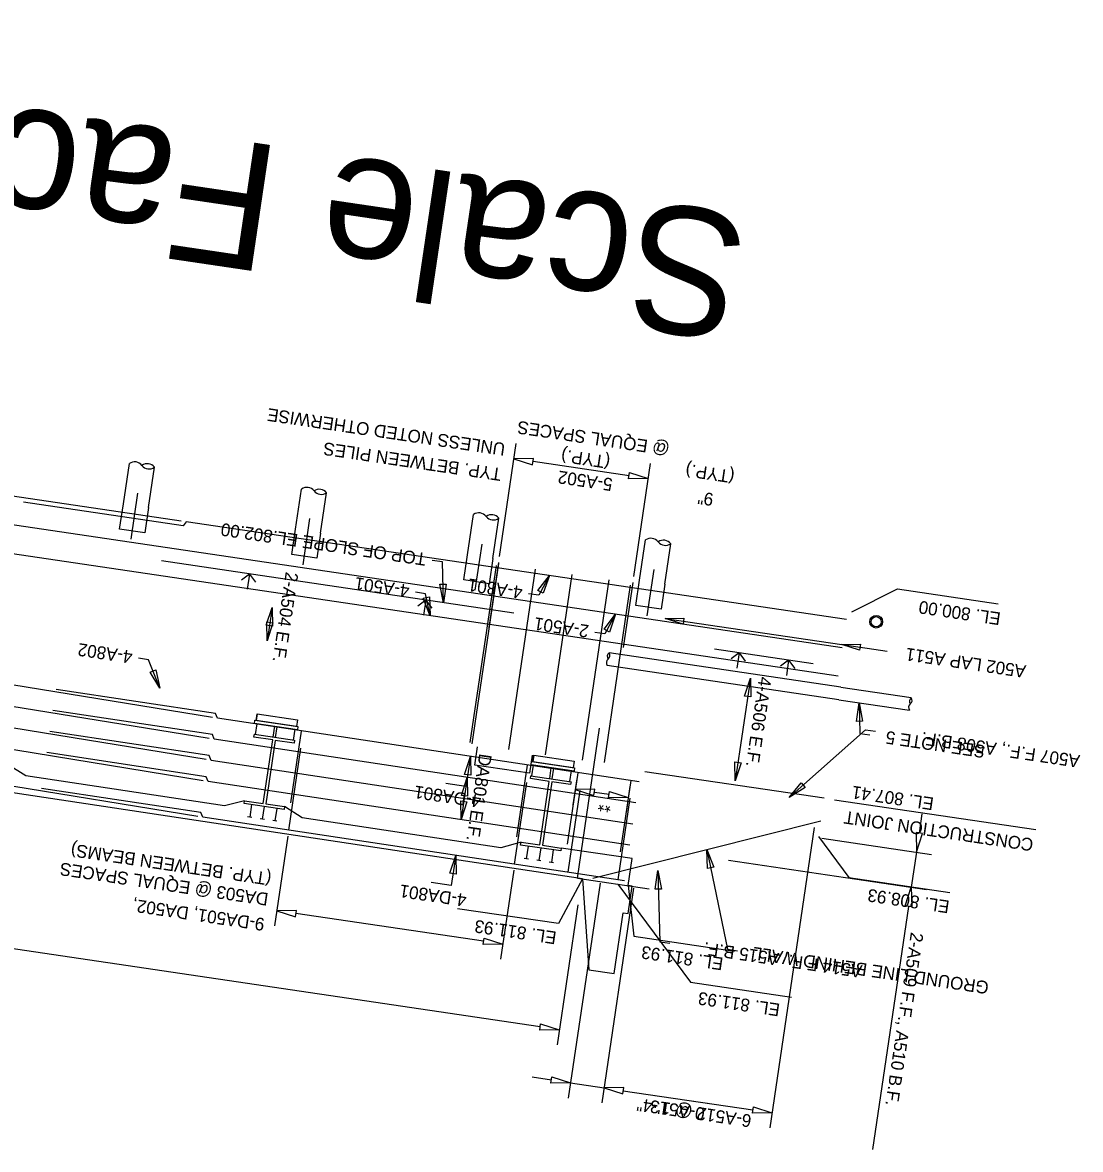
# Model space of a CAD drawing. Extents: x 1467956 to 1469946, y 573734 to 574139.
# Drawn here: x 1469049.93 to 1469091.48, y 574051.68 to 574095.95 of the extents above; entities that cross this region are included whole.
import ezdxf

# ---------------------------------------------------------------- set-up
doc = ezdxf.new("R2010")
doc.units = 0
for name, color, linetype in [('BR_P_Beam_Object', 7, 'Continuous'), ('BR_P_Beam_Stl_Det_Hidden', 7, 'Continuous'), ('BR_P_Brg_Pad_Object', 7, 'Continuous'), ('BR_P_Dia_Hidden', 7, 'Continuous'), ('BR_P_Dia_Reinforcing', 7, 'Continuous'), ('BR_P_Gen_NonPerf_Pipe', 7, 'Continuous'), ('BR_P_Gen_Text', 7, 'Continuous'), ('BR_P_Slab_Object', 7, 'Continuous'), ('BR_P_Sub_Const_Joint', 7, 'Continuous'), ('BR_P_Sub_Deep_Centerline', 7, 'Continuous'), ('BR_P_Sub_Deep_Hidden', 7, 'Continuous'), ('BR_P_Sub_Deep_Object', 7, 'Continuous'), ('BR_P_Sub_Foot_Reinforcing', 7, 'Continuous'), ('BR_P_Sub_Hidden', 7, 'Continuous'), ('BR_P_Sub_Text', 7, 'Continuous'), ('Default', 7, 'Continuous')]:
    doc.layers.add(name, color=color, linetype=linetype)

# ---------------------------------------------------------------- blocks, each defined once
blk = doc.blocks.new('arrowOhio')
at = {"layer": 'Default'}
blk.add_lwpolyline([(0.00381, 0.000635), (0.00381, -0.000635), (0, 0)], close=True, dxfattribs=at)

msp = doc.modelspace()

# ---------------------------------------------------------------- linework, layer by layer
at = {"layer": 'BR_P_Beam_Object'}
for p, q in [((1469059.015, 574067.879), (1469059.032, 574067.992)), ((1469059.753, 574067.77), (1469059.015, 574067.879)), ((1469059.032, 574067.992), (1469060.607, 574067.759)), ((1469059.384, 574065.276), (1469059.753, 574067.77)), ((1469059.853, 574067.755), (1469059.483, 574065.261)), ((1469060.591, 574067.646), (1469059.853, 574067.755)), ((1469060.607, 574067.759), (1469060.591, 574067.646)), ((1469069.878, 574066.251), (1469069.895, 574066.364)), ((1469070.616, 574066.141), (1469069.878, 574066.251)), ((1469069.895, 574066.364), (1469071.47, 574066.131)), ((1469070.247, 574063.648), (1469070.616, 574066.141)), ((1469070.715, 574066.127), (1469070.346, 574063.633)), ((1469071.453, 574066.018), (1469070.715, 574066.127)), ((1469071.47, 574066.131), (1469071.453, 574066.018)), ((1469058.629, 574065.272), (1469058.646, 574065.385)), ((1469060.205, 574065.039), (1469058.629, 574065.272)), ((1469058.646, 574065.385), (1469059.384, 574065.276)), ((1469058.922, 574065.229), (1469058.849, 574064.734)), ((1469059.417, 574065.155), (1469059.344, 574064.661)), ((1469059.483, 574065.261), (1469060.221, 574065.152)), ((1469059.912, 574065.082), (1469059.838, 574064.588)), ((1469060.221, 574065.152), (1469060.205, 574065.039)), ((1469058.932, 574064.722), (1469058.767, 574064.746)), ((1469059.426, 574064.649), (1469059.261, 574064.673)), ((1469059.921, 574064.575), (1469059.756, 574064.6)), ((1469069.492, 574063.644), (1469069.509, 574063.757)), ((1469069.509, 574063.757), (1469070.247, 574063.648)), ((1469071.067, 574063.411), (1469069.492, 574063.644)), ((1469069.785, 574063.6), (1469069.712, 574063.106)), ((1469070.279, 574063.527), (1469070.206, 574063.033)), ((1469070.346, 574063.633), (1469071.084, 574063.524)), ((1469070.774, 574063.454), (1469070.701, 574062.959)), ((1469071.084, 574063.524), (1469071.067, 574063.411)), ((1469069.794, 574063.094), (1469069.629, 574063.118)), ((1469070.289, 574063.02), (1469070.124, 574063.045)), ((1469070.783, 574062.947), (1469070.618, 574062.972))]:
    msp.add_line(p, q, dxfattribs=at)
at = {"layer": 'BR_P_Beam_Stl_Det_Hidden'}
for p, q in [((1469059.073, 574067.986), (1469059.136, 574068.409)), ((1469059.77, 574067.883), (1469059.833, 574068.306)), ((1469059.869, 574067.868), (1469059.932, 574068.291)), ((1469060.566, 574067.765), (1469060.629, 574068.188)), ((1469069.936, 574066.358), (1469069.998, 574066.78)), ((1469070.633, 574066.255), (1469070.695, 574066.677)), ((1469070.732, 574066.24), (1469070.794, 574066.663)), ((1469071.429, 574066.137), (1469071.491, 574066.559))]:
    msp.add_line(p, q, dxfattribs=at)
at = {"layer": 'BR_P_Brg_Pad_Object'}
for p, q in [((1469059.145, 574068.797), (1469059.107, 574068.539)), ((1469059.039, 574068.423), (1469059.057, 574068.547)), ((1469060.726, 574068.173), (1469059.039, 574068.423)), ((1469059.057, 574068.547), (1469060.744, 574068.297)), ((1469060.733, 574068.562), (1469060.694, 574068.304)), ((1469060.744, 574068.297), (1469060.726, 574068.173)), ((1469069.901, 574066.795), (1469069.92, 574066.918)), ((1469069.92, 574066.918), (1469071.606, 574066.669)), ((1469070.007, 574067.169), (1469069.969, 574066.911)), ((1469071.595, 574066.934), (1469071.557, 574066.676)), ((1469071.588, 574066.545), (1469069.901, 574066.795)), ((1469071.606, 574066.669), (1469071.588, 574066.545))]:
    msp.add_line(p, q, dxfattribs=at)
for points in [[(1469060.733, 574068.562), (1469060.694, 574068.304), (1469059.107, 574068.539), (1469059.145, 574068.797)], [(1469071.595, 574066.934), (1469071.557, 574066.676), (1469069.969, 574066.911), (1469070.007, 574067.169)]]:
    msp.add_lwpolyline(points, close=True, dxfattribs=at)
at = {"layer": 'BR_P_Dia_Hidden'}
for q in [(1469072.594, 574068.231), (1469074.541, 574061.928)]:
    msp.add_line((1469071.723, 574062.345), q, dxfattribs=at)
at = {"layer": 'BR_P_Dia_Reinforcing'}
for p, q in [((1469057.382, 574068.654), (1469035.698, 574072.185)), ((1469057.26, 574067.826), (1469035.575, 574071.358)), ((1469057.137, 574066.999), (1469035.453, 574070.53)), ((1469057.015, 574066.171), (1469035.33, 574069.703)), ((1469057.506, 574068.81), (1469051.244, 574069.755)), ((1469057.384, 574067.983), (1469051.121, 574068.928)), ((1469057.58, 574068.624), (1469057.506, 574068.81)), ((1469074.146, 574066.124), (1469057.58, 574068.624)), ((1469056.807, 574064.767), (1469035.123, 574068.299)), ((1469057.261, 574067.155), (1469050.999, 574068.1)), ((1469057.457, 574067.797), (1469057.384, 574067.983)), ((1469074.023, 574065.297), (1469057.457, 574067.797)), ((1469060.87, 574068.11), (1469060.455, 574065.302)), ((1469057.139, 574066.328), (1469050.876, 574067.273)), ((1469060.38, 574064.229), (1469060.856, 574067.444)), ((1469057.335, 574066.969), (1469057.261, 574067.155)), ((1469073.901, 574064.469), (1469057.335, 574066.969)), ((1469069.744, 574066.776), (1469069.329, 574063.968)), ((1469071.733, 574066.482), (1469071.317, 574063.674)), ((1469057.212, 574066.142), (1469057.139, 574066.328)), ((1469073.778, 574063.642), (1469057.212, 574066.142)), ((1469069.253, 574062.89), (1469069.729, 574066.105)), ((1469073.817, 574066.181), (1469073.402, 574063.373)), ((1469056.931, 574064.924), (1469050.669, 574065.869)), ((1469071.356, 574062.572), (1469071.832, 574065.787)), ((1469073.323, 574062.275), (1469073.799, 574065.49)), ((1469057.005, 574064.738), (1469056.931, 574064.924)), ((1469073.571, 574062.238), (1469057.005, 574064.738))]:
    msp.add_line(p, q, dxfattribs=at)
at = {"layer": 'BR_P_Gen_NonPerf_Pipe'}
for p, q in [((1469082.065, 574069.842), (1469084.835, 574069.432)), ((1469081.992, 574069.347), (1469084.762, 574068.937))]:
    msp.add_line(p, q, dxfattribs=at)
for radius in [0.25, 0.2]:
    msp.add_circle((1469083.457, 574072.416), radius, dxfattribs=at)
for centre, start, end in [((1469084.91, 574069.041), 127.976, 215.1816), ((1469084.947, 574069.289), 127.976, 215.1816), ((1469084.687, 574069.327), 307.976, 35.1816)]:
    msp.add_arc(centre, 0.181, start, end, dxfattribs=at)
at = {"layer": 'BR_P_Gen_Text'}
for p, q in [((1469068.66, 574074.975), (1469069.317, 574079.412)), ((1469073.753, 574078.149), (1469069.981, 574078.707)), ((1469073.936, 574074.194), (1469074.593, 574078.631)), ((1469066.416, 574074.762), (1469066.021, 574074.821)), ((1469066.461, 574073.163), (1469066.416, 574074.762)), ((1469070.622, 574074.232), (1469070.203, 574073.458)), ((1469065.756, 574073.513), (1469065.36, 574073.572)), ((1469065.933, 574072.651), (1469065.756, 574073.513)), ((1469070.203, 574073.458), (1469069.807, 574073.516)), ((1469082.505, 574072.809), (1469084.293, 574073.704)), ((1469084.293, 574073.704), (1469088.25, 574073.118)), ((1469059.729, 574072.98), (1469059.535, 574071.671)), ((1469073.221, 574072.709), (1469072.802, 574071.936)), ((1469075.166, 574072.548), (1469082.103, 574071.521)), ((1469072.802, 574071.936), (1469072.407, 574071.994)), ((1469082.103, 574071.521), (1469083.101, 574071.373)), ((1469082.103, 574071.521), (1469082.103, 574071.521)), ((1469083.101, 574071.373), (1469083.892, 574071.256)), ((1469054.879, 574070.92), (1469054.484, 574070.979)), ((1469055.321, 574069.804), (1469054.879, 574070.92)), ((1469070.259, 574056.497), (1468978.025, 574070.152)), ((1469078.518, 574070.198), (1469077.921, 574066.166)), ((1469082.784, 574069.23), (1469082.817, 574068.03)), ((1469080.043, 574065.514), (1469083.035, 574068.169)), ((1469083.035, 574068.169), (1469083.431, 574068.11)), ((1469082.817, 574068.03), (1469083.212, 574067.972)), ((1469067.52, 574067.124), (1469067.344, 574065.937)), ((1469067.344, 574065.937), (1469066.552, 574066.054)), ((1469067.397, 574066.297), (1469067.152, 574064.642)), ((1469071.698, 574066.244), (1469071.547, 574065.228)), ((1469073.782, 574065.943), (1469073.631, 574064.919)), ((1469072.967, 574065.624), (1469072.387, 574065.71)), ((1469085.154, 574064.115), (1469085.265, 574064.867)), ((1469081.024, 574064.332), (1469079.277, 574052.533)), ((1469060.345, 574063.991), (1469059.823, 574060.47)), ((1469081.197, 574063.976), (1469082.389, 574062.37)), ((1469081.323, 574063.914), (1469085.636, 574063.276)), ((1469076.809, 574063.465), (1469077.612, 574059.546)), ((1469085.043, 574063.364), (1469084.838, 574061.983)), ((1469066.944, 574063.238), (1469066.768, 574062.051)), ((1469077.653, 574063.047), (1469085.432, 574061.895)), ((1469069.218, 574062.652), (1469068.7, 574059.155)), ((1469074.877, 574062.641), (1469074.955, 574059.842)), ((1469066.768, 574062.051), (1469065.977, 574062.168)), ((1469071.925, 574062.316), (1469070.973, 574060.557)), ((1469072.612, 574062.14), (1469071.363, 574053.705)), ((1469073.308, 574062.111), (1469076.168, 574058.256)), ((1469073.711, 574062.051), (1469073.941, 574060.064)), ((1469082.389, 574062.37), (1469086.346, 574061.784)), ((1469073.931, 574061.944), (1469072.682, 574053.51)), ((1469073.931, 574061.944), (1469072.682, 574053.51)), ((1469070.973, 574060.557), (1469067.017, 574061.142)), ((1469071.737, 574061.289), (1469070.923, 574055.792)), ((1469084.727, 574061.231), (1469083.314, 574051.684)), ((1469068.037, 574059.86), (1469060.663, 574060.952)), ((1469073.941, 574060.064), (1469077.897, 574059.478)), ((1469074.955, 574059.842), (1469075.35, 574059.784)), ((1469077.612, 574059.546), (1469078.008, 574059.488)), ((1469076.168, 574058.256), (1469080.125, 574057.671)), ((1469070.699, 574054.41), (1469069.948, 574054.521)), ((1469071.451, 574054.299), (1469072.77, 574054.103)), ((1469073.522, 574053.992), (1469078.613, 574053.238)), ((1469073.522, 574053.992), (1469076.997, 574053.478))]:
    msp.add_line(p, q, dxfattribs=at)
for points in [[(1469069.962, 574078.582), (1469069.999, 574078.832), (1469069.229, 574078.818)], [(1469073.734, 574078.023), (1469073.772, 574078.274), (1469074.505, 574078.037)], [(1469072.368, 574065.585), (1469072.405, 574065.835), (1469071.635, 574065.821)], [(1469072.948, 574065.499), (1469072.985, 574065.749), (1469073.718, 574065.513)], [(1469085.279, 574064.097), (1469085.029, 574064.134), (1469085.043, 574063.364)], [(1469084.852, 574061.213), (1469084.602, 574061.25), (1469084.838, 574061.983)], [(1469060.645, 574060.827), (1469060.682, 574061.077), (1469059.911, 574061.063)], [(1469068.018, 574059.735), (1469068.055, 574059.986), (1469068.788, 574059.749)], [(1469070.241, 574056.372), (1469070.278, 574056.622), (1469071.011, 574056.386)], [(1469070.681, 574054.285), (1469070.718, 574054.535), (1469071.451, 574054.299)], [(1469073.503, 574053.867), (1469073.541, 574054.117), (1469072.77, 574054.103)], [(1469073.503, 574053.867), (1469073.541, 574054.117), (1469072.77, 574054.103)], [(1469078.595, 574053.113), (1469078.632, 574053.364), (1469079.365, 574053.127)]]:
    msp.add_lwpolyline(points, close=True, dxfattribs=at)
at = {"layer": 'BR_P_Slab_Object'}
for p, q in [((1469071.925, 574062.316), (1469040.98, 574066.988)), ((1469073.868, 574063.112), (1469071.084, 574063.524)), ((1469073.711, 574062.048), (1469073.868, 574063.112)), ((1469071.925, 574062.316), (1469072.173, 574058.741)), ((1469071.925, 574062.316), (1469071.925, 574062.316)), ((1469071.925, 574062.316), (1469071.925, 574062.316)), ((1469073.876, 574062.027), (1469073.711, 574062.051)), ((1469073.718, 574060.955), (1469073.876, 574062.027)), ((1469073.165, 574058.594), (1469073.519, 574060.984)), ((1469073.519, 574060.984), (1469073.718, 574060.955)), ((1469072.173, 574058.741), (1469073.165, 574058.594))]:
    msp.add_line(p, q, dxfattribs=at)
for points in [[(1469058.646, 574065.385), (1469057.857, 574065.177), (1469050.054, 574066.355), (1469049.36, 574066.79)], [(1469069.509, 574063.757), (1469068.718, 574063.537), (1469060.915, 574064.715), (1469060.221, 574065.152)]]:
    msp.add_lwpolyline(points, dxfattribs=at)
at = {"layer": 'BR_P_Sub_Const_Joint'}
msp.add_line((1469081.42, 574065.479), (1469074.373, 574066.522), dxfattribs=at)
at = {"layer": 'BR_P_Sub_Deep_Centerline'}
for p, q in [((1469054.187, 574075.654), (1469054.455, 574077.467)), ((1469060.946, 574074.653), (1469061.215, 574076.467)), ((1469067.706, 574073.652), (1469067.974, 574075.466)), ((1469074.466, 574072.652), (1469074.734, 574074.465))]:
    msp.add_line(p, q, dxfattribs=at)
at = {"layer": 'BR_P_Sub_Deep_Hidden'}
for p, q in [((1469053.741, 574076.057), (1469053.887, 574077.046)), ((1469054.877, 574076.9), (1469054.73, 574075.91)), ((1469054.73, 574075.91), (1469053.741, 574076.057)), ((1469060.501, 574075.056), (1469060.647, 574076.045)), ((1469061.636, 574075.899), (1469061.49, 574074.91)), ((1469061.49, 574074.91), (1469060.501, 574075.056)), ((1469067.26, 574074.055), (1469067.407, 574075.045)), ((1469068.396, 574074.898), (1469068.249, 574073.909)), ((1469068.249, 574073.909), (1469067.26, 574074.055)), ((1469074.02, 574073.055), (1469074.166, 574074.044)), ((1469075.155, 574073.897), (1469075.009, 574072.908)), ((1469075.009, 574072.908), (1469074.02, 574073.055))]:
    msp.add_line(p, q, dxfattribs=at)
at = {"layer": 'BR_P_Sub_Deep_Object'}
for p, q in [((1469053.887, 574077.046), (1469054.122, 574078.629)), ((1469054.877, 574076.9), (1469055.111, 574078.482)), ((1469060.647, 574076.045), (1469060.881, 574077.628)), ((1469061.636, 574075.899), (1469061.871, 574077.482)), ((1469067.407, 574075.045), (1469067.641, 574076.627)), ((1469068.396, 574074.898), (1469068.63, 574076.481)), ((1469074.166, 574074.044), (1469074.401, 574075.627)), ((1469075.155, 574073.897), (1469075.39, 574075.48))]:
    msp.add_line(p, q, dxfattribs=at)
for centre, start, end in [((1469054.331, 574078.332), 37.976, 125.1816), ((1469054.825, 574078.259), 37.976, 125.1816), ((1469054.902, 574078.779), 217.976, 305.1816), ((1469061.09, 574077.332), 37.976, 125.1816), ((1469061.585, 574077.258), 37.976, 125.1816), ((1469061.662, 574077.778), 217.976, 305.1816), ((1469067.85, 574076.331), 37.976, 125.1816), ((1469068.344, 574076.258), 37.976, 125.1816), ((1469068.421, 574076.777), 217.976, 305.1816), ((1469074.609, 574075.33), 37.976, 125.1816), ((1469075.104, 574075.257), 37.976, 125.1816), ((1469075.181, 574075.776), 217.976, 305.1816)]:
    msp.add_arc(centre, 0.362, start, end, dxfattribs=at)
at = {"layer": 'BR_P_Sub_Foot_Reinforcing'}
for p, q in [((1469068.524, 574074.626), (1469067.494, 574067.667)), ((1469068.619, 574074.697), (1469067.57, 574067.614)), ((1469068.625, 574074.738), (1469068.247, 574072.182)), ((1469070.063, 574074.483), (1469069.014, 574067.4)), ((1469071.507, 574074.269), (1469070.458, 574067.186)), ((1469072.951, 574074.055), (1469071.903, 574066.972)), ((1469073.901, 574073.957), (1469073.522, 574071.401)), ((1469073.8, 574073.845), (1469072.77, 574066.886))]:
    msp.add_line(p, q, dxfattribs=at)
for points in [[(1469056.161, 574076.372), (1469030.427, 574080.182), (1469030.303, 574080.026), (1469024.038, 574080.953)], [(1469082.126, 574071.391), (1469046.506, 574076.665), (1469046.433, 574076.85), (1469043.3, 574077.314)], [(1469082.291, 574072.504), (1469056.359, 574076.343), (1469056.235, 574076.186), (1469049.97, 574077.114)], [(1469081.962, 574070.278), (1469046.341, 574075.552), (1469046.268, 574075.738), (1469043.135, 574076.201)]]:
    msp.add_lwpolyline(points, dxfattribs=at)
at = {"layer": 'BR_P_Sub_Hidden'}
for p, q in [((1469082.065, 574069.842), (1469072.965, 574071.189)), ((1469081.992, 574069.347), (1469072.891, 574070.694)), ((1469072.33, 574062.337), (1469081.288, 574064.593))]:
    msp.add_line(p, q, dxfattribs=at)
for centre, start, end in [((1469073.04, 574070.799), 127.976, 215.1816), ((1469073.076, 574071.046), 127.976, 215.1816), ((1469072.817, 574071.085), 307.976, 35.1816)]:
    msp.add_arc(centre, 0.181, start, end, dxfattribs=at)
at = {"layer": 'BR_P_Sub_Text'}
for p, q in [((1469069.23, 574072.753), (1469055.381, 574074.803)), ((1469058.844, 574074.29), (1469058.522, 574074.052)), ((1469058.844, 574074.29), (1469058.756, 574073.697)), ((1469058.844, 574074.29), (1469059.082, 574073.969)), ((1469065.768, 574073.265), (1469065.447, 574073.027)), ((1469065.768, 574073.265), (1469065.68, 574072.672)), ((1469065.768, 574073.265), (1469066.006, 574072.944)), ((1469080.988, 574070.759), (1469077.107, 574071.334)), ((1469078.078, 574071.19), (1469077.756, 574070.952)), ((1469078.078, 574071.19), (1469077.99, 574070.597)), ((1469078.078, 574071.19), (1469078.316, 574070.869)), ((1469080.018, 574070.903), (1469079.697, 574070.665)), ((1469080.018, 574070.903), (1469079.93, 574070.309)), ((1469080.018, 574070.903), (1469080.256, 574070.582)), ((1469081.815, 574065.421), (1469089.729, 574064.249))]:
    msp.add_line(p, q, dxfattribs=at)
msp.add_lwpolyline([(1469069.941, 574067.179), (1469069.836, 574066.468), (1469067.692, 574066.785), (1469067.798, 574067.496)], dxfattribs=at)

# ---------------------------------------------------------------- block references
at = {"layer": 'BR_P_Gen_Text'}
for p, xscale, yscale, rotation in [((1469070.622, 574074.232), 191.49568, 191.49568000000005, -118.42123067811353), ((1469066.461, 574073.163), 191.49568, 191.49568, 91.57876932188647), ((1469065.933, 574072.651), 191.49568000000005, 191.49568, 101.57876932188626), ((1469059.729, 574072.98), 191.49568000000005, 191.49568, -98.42123067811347), ((1469073.221, 574072.709), 191.49568, 191.49568000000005, -118.42123067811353), ((1469075.166, 574072.548), 191.49568000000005, 191.49568, -8.421230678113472), ((1469059.535, 574071.671), 191.49568000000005, 191.49568, 81.57876932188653), ((1469082.103, 574071.521), 191.49568000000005, 191.49568, -8.421230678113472), ((1469055.321, 574069.804), 191.49568000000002, 191.49568000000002, 111.57876932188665), ((1469078.518, 574070.198), 191.49568000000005, 191.49568, -98.42123067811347), ((1469082.784, 574069.23), 191.49568000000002, 191.49568000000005, -88.42123067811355), ((1469067.52, 574067.124), 191.49568000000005, 191.49568, -98.42123067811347), ((1469077.921, 574066.166), 191.49568000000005, 191.49568, 81.57876932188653), ((1469067.397, 574066.297), 191.49568000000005, 191.49568, -98.42123067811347), ((1469080.043, 574065.514), 191.49568000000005, 191.49568, 41.57876932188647), ((1469067.152, 574064.642), 191.49568000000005, 191.49568, 81.57876932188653), ((1469076.809, 574063.465), 191.49568000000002, 191.49568000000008, -78.42123067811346), ((1469066.944, 574063.238), 191.49568000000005, 191.49568, -98.42123067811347), ((1469074.877, 574062.641), 191.49568, 191.49568000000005, -88.42123067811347)]:
    msp.add_blockref('arrowOhio', p, dxfattribs=dict(at, xscale=xscale, yscale=yscale, rotation=rotation))

# ---------------------------------------------------------------- texts
for s, height, rotation, p in [('Scale Factor = 48', 4.99999, 171.5788, (1469078.57, 574088.343)), ('UNLESS NOTED OTHERWISE', 0.5, 171.5788, (1469068.914, 574079.425)), (' @ EQUAL SPACES', 0.5, 171.5788, (1469075.553, 574079.398)), ('TYP. BETWEEN PILES', 0.5, 171.5788, (1469068.768, 574078.436)), ('(TYP.)', 0.5, 171.5788, (1469073.032, 574078.912)), ('5-A502', 0.5, 171.5788, (1469073.131, 574078.038)), ('(TYP.)', 0.5, 171.5788, (1469077.918, 574078.341)), ('9"', 0.5, 171.5788, (1469077.094, 574077.452)), ('TOP OF SLOPE EL.802.00', 0.5, 171.5788, (1469065.81, 574075.105)), ('2-A504 E.F.', 0.5, 261.5788, (1469060.267, 574074.39)), ('4-A501', 0.5, 171.5788, (1469065.149, 574073.856)), ('4-A801', 0.5, 171.5788, (1469069.596, 574073.8)), ('EL. 800.00', 0.5, 171.5788, (1469088.373, 574072.771)), ('2-A501', 0.5, 171.5788, (1469072.196, 574072.278)), ('4-A802', 0.5, 171.5788, (1469054.273, 574071.263)), ('A502 LAP A511', 0.5, 171.5788, (1469089.366, 574070.698)), ('4-A506 E.F.', 0.5, 261.5788, (1469078.859, 574070.279)), ('SEE NOTE 5', 0.5, 171.5788, (1469087.769, 574067.55)), ('A507 F.F., A508 B.F.', 0.5, 171.5788, (1469091.483, 574067.171)), ('DA801 E.F.', 0.5, 261.5788, (1469067.868, 574067.254)), ('4-DA801', 0.5, 171.5788, (1469067.968, 574065.596)), ('EL. 807.41', 0.5, 171.5788, (1469085.746, 574065.5)), ('**', 0.5, 171.5788, (1469073.089, 574065.404)), ('CONSTRUCTION JOINT', 0.5, 171.5788, (1469089.659, 574063.889)), ('(TYP. BETWEEN BEAMS)', 0.5, 171.5788, (1469059.726, 574062.54)), ('DA503 @ EQUAL SPACES', 0.5, 171.5788, (1469059.608, 574061.749)), ('4-DA801', 0.5, 171.5788, (1469067.392, 574061.71)), ('9-DA501, DA502,', 0.5, 171.5788, (1469059.462, 574060.76)), ('EL. 808.93', 0.5, 171.5788, (1469086.363, 574061.452)), ('EL. 811.93', 0.5, 171.5788, (1469070.926, 574060.234)), ('2-A509 F.F., A510 B.F.', 0.5, 261.5788, (1469084.823, 574060.235)), ('A514 F.F., A515 B.F.', 0.5, 171.5788, (1469082.932, 574058.914)), ('EL. 811.93', 0.5, 171.5788, (1469077.477, 574059.211)), ('GROUND LINE BEHIND WALL', 0.5, 171.5788, (1469087.908, 574058.275)), ('EL. 811.93', 0.5, 171.5788, (1469079.704, 574057.403)), ('6-A512 @ 1\'-4"', 0.5, 171.5788, (1469078.584, 574053.04)), ('0-A513', 0.5, 171.5788, (1469076.751, 574053.312))]:
    msp.add_text(s, height=height, rotation=rotation, dxfattribs=at).set_placement(p)

doc.saveas('drawing.dxf')
